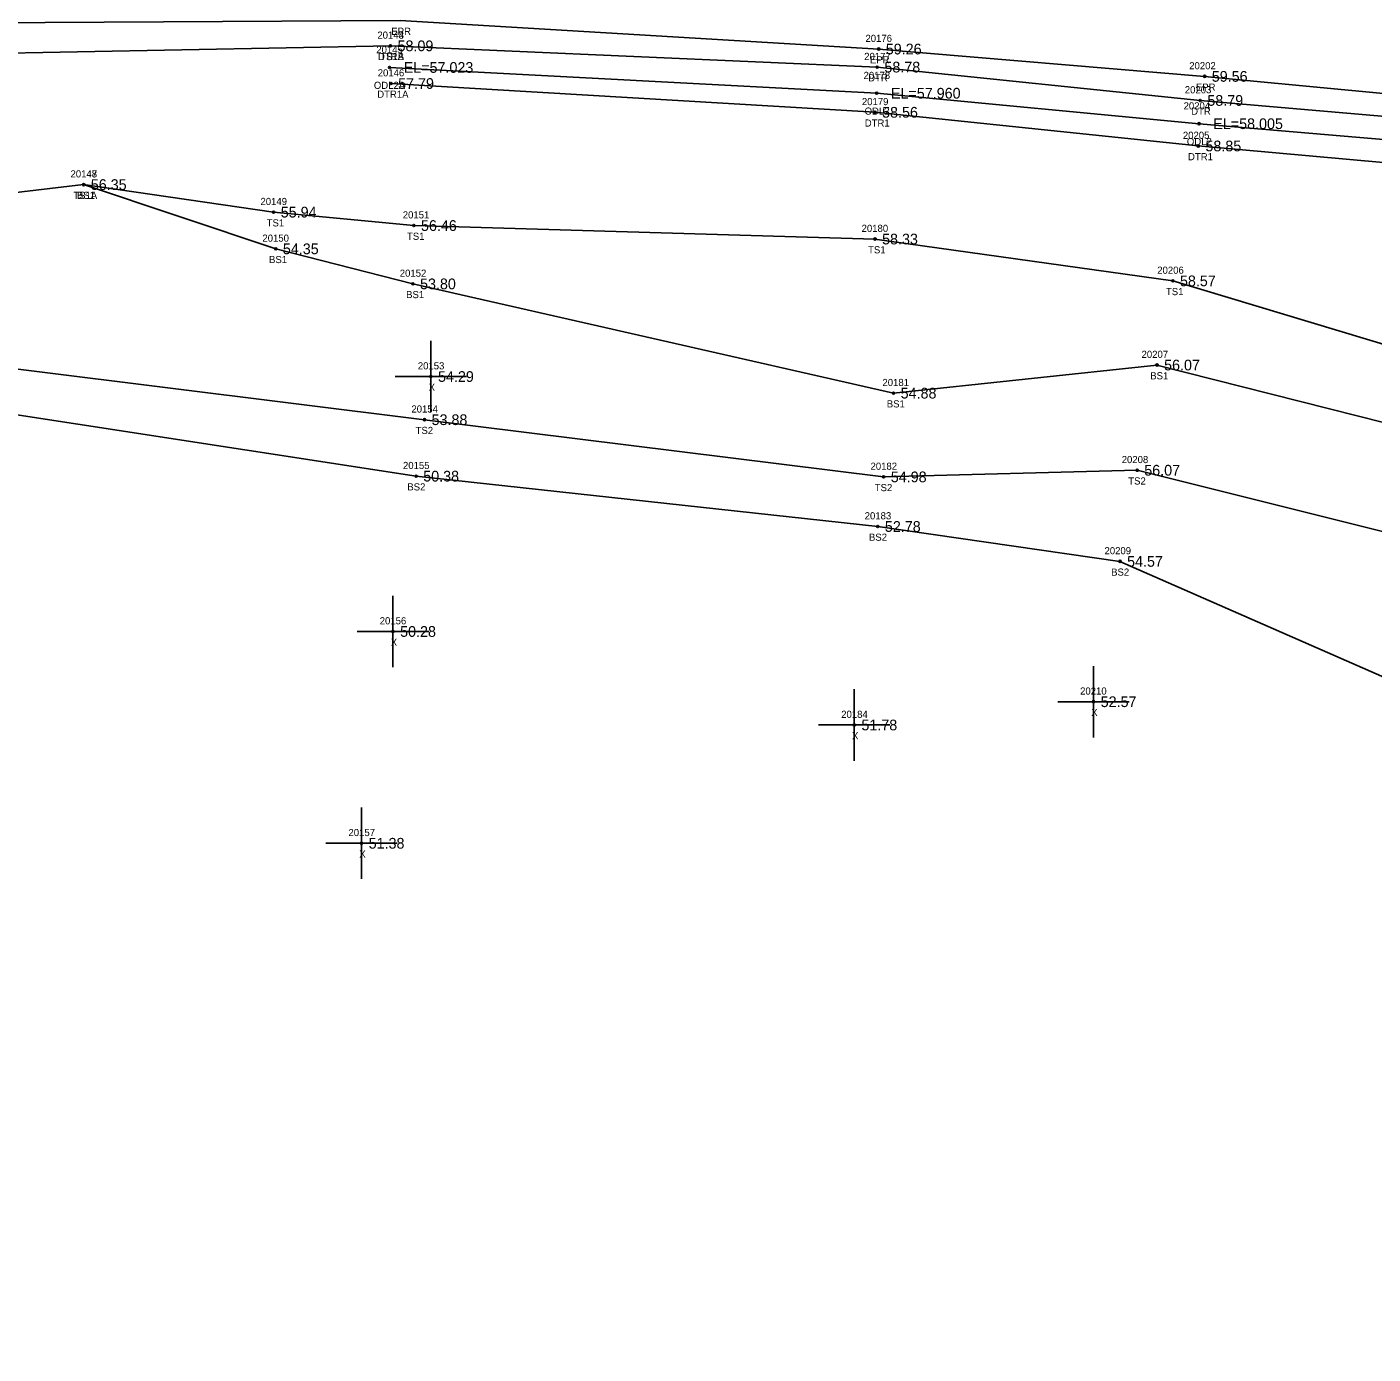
# Model space of a CAD drawing. Extents: x 2420351 to 2422725, y 845330 to 846558.
# Drawn here: x 2420630.1 to 2420818.7, y 845524.4 to 845710.4 of the extents above; entities that cross this region are included whole.
import ezdxf

# ---------------------------------------------------------------- set-up
doc = ezdxf.new("R2010")
doc.units = 0
for name, color, linetype in [('RD_DTM_BkLn2', 7, 'Continuous'), ('RD_DTM_BkLn_txCode', 7, 'Continuous'), ('RD_EX_H2O', 7, 'Continuous'), ('RD_EX_H2O_txCode', 7, 'Continuous'), ('RD_EX_Misc', 7, 'Continuous'), ('RD_EX_Misc_txCode', 7, 'Continuous'), ('RD_EX_Road', 7, 'Continuous'), ('RD_EX_Road_txCode', 7, 'Continuous'), ('RD_EX_TX_H2O_ELEV', 7, 'Continuous'), ('RD_EX_TX_Misc_ELEV', 7, 'Continuous'), ('RD_EX_TX_Road_ELEV', 7, 'Continuous'), ('RD_SMD_Locator', 7, 'Continuous')]:
    doc.layers.add(name, color=color, linetype=linetype)

msp = doc.modelspace()

# ---------------------------------------------------------------- linework, layer by layer
at = {"layer": 'RD_DTM_BkLn2'}
for points in [[(2420390.61, 845669.92), (2420441.98, 845686.33), (2420494.54, 845693.53), (2420554.96, 845697.51), (2420607.89, 845706.33), (2420681.02, 845707.72)], [(2420391.68, 845656.64), (2420445.21, 845668.26), (2420499.47, 845673.15), (2420555.79, 845685.67), (2420611.25, 845685.1), (2420638.03, 845688.28), (2420664.95, 845679.28), (2420684.17, 845674.37), (2420751.52, 845659.06), (2420788.44, 845663), (2420892.57, 845636.64), (2420995.04, 845591.46), (2421010.85, 845555.52)], [(2420638.03, 845688.28), (2420664.65, 845684.42), (2420684.3, 845682.54), (2420748.92, 845680.65), (2420790.66, 845674.79), (2420895.81, 845643.13), (2420998.36, 845598.73), (2421012.82, 845561.7)], [(2420554.48, 845663.6), (2420612.71, 845664.41), (2420685.79, 845655.34), (2420750.14, 845647.33), (2420785.66, 845648.26), (2420885.87, 845623.22), (2421008.49, 845539.14)], [(2420554.18, 845658.61), (2420613.14, 845658.42), (2420684.62, 845647.43), (2420749.31, 845640.38), (2420783.25, 845635.49), (2420872.47, 845596.38), (2421005.56, 845524.43)]]:
    msp.add_lwpolyline(points, dxfattribs=at)
at = {"layer": 'RD_EX_H2O'}
for points in [[(2420681.02, 845707.72), (2420749.24, 845704.74), (2420794.5, 845700.07), (2420899.98, 845690.96), (2421017.54, 845678.31), (2421112.89, 845668.07), (2421174.6, 845666.39), (2421234.64, 845664.08), (2421293.38, 845665.28), (2421351.67, 845667.88), (2421422.34, 845677.35), (2421426.88, 845673.47), (2421424.22, 845667.22)], [(2420680.88, 845704.69), (2420749.16, 845701.08), (2420794.33, 845696.81), (2420899.79, 845687.85), (2421017.53, 845674.81), (2421112.48, 845665.13), (2421174.04, 845661.58), (2421234.82, 845660.24), (2421294.09, 845659.38), (2421352.01, 845663.24), (2421417.66, 845672.42), (2421424.72, 845673.17)], [(2420681.1, 845702.44), (2420748.92, 845698.41), (2420794.23, 845693.69), (2420899.45, 845684.25), (2421017.43, 845671.31), (2421111.87, 845660.39), (2421174.2, 845656.63), (2421235.06, 845654.38), (2421294.9, 845653.67), (2421353.19, 845655.89), (2421424.22, 845667.22)]]:
    msp.add_lwpolyline(points, dxfattribs=at)
at = {"layer": 'RD_EX_Misc'}
for p, q in [((2420686.69, 845656.39), (2420686.69, 845666.39)), ((2420681.69, 845661.39), (2420691.69, 845661.39)), ((2420681.38, 845620.67), (2420681.38, 845630.67)), ((2420676.38, 845625.67), (2420686.38, 845625.67)), ((2420779.55, 845610.83), (2420779.55, 845620.83)), ((2420746.02, 845607.57), (2420746.02, 845617.57)), ((2420774.55, 845615.83), (2420784.55, 845615.83)), ((2420741.02, 845612.57), (2420751.02, 845612.57)), ((2420676.97, 845591), (2420676.97, 845601)), ((2420671.97, 845596), (2420681.97, 845596))]:
    msp.add_line(p, q, dxfattribs=at)
at = {"layer": 'RD_EX_Road'}
msp.add_lwpolyline([(2420388.28, 845680.39), (2420441.29, 845692.04), (2420492.62, 845700.7), (2420553.92, 845707.41), (2420607.69, 845710.85), (2420682.38, 845711.26), (2420749.44, 845707.27), (2420795.12, 845703.44), (2420900.28, 845693.42), (2421017.17, 845682.19), (2421113.9, 845672.97), (2421174.87, 845668.16), (2421234.59, 845666.13), (2421293, 845667.25), (2421351.24, 845671.5), (2421419.82, 845681.17), (2421463.19, 845688.63), (2421558.82, 845713.18), (2421614.57, 845730.45), (2421670.73, 845751.42), (2421735.61, 845780.5), (2421750.75, 845787.87), (2421744.67, 845798.22), (2421739.21, 845808.11)], dxfattribs=at)
at = {"layer": 'RD_SMD_Locator'}
for centre in [(2420681.02, 845707.72), (2420681.02, 845707.72), (2420749.44, 845707.27), (2420680.88, 845704.69), (2420749.24, 845704.74), (2420795.12, 845703.44), (2420681.1, 845702.44), (2420749.16, 845701.08), (2420794.5, 845700.07), (2420748.92, 845698.41), (2420794.33, 845696.81), (2420794.23, 845693.69), (2420638.03, 845688.28), (2420638.03, 845688.28), (2420664.65, 845684.42), (2420684.3, 845682.54), (2420748.92, 845680.65), (2420664.95, 845679.28), (2420790.66, 845674.79), (2420684.17, 845674.37), (2420686.69, 845661.39), (2420788.44, 845663), (2420751.52, 845659.06), (2420685.79, 845655.34), (2420785.66, 845648.26), (2420684.62, 845647.43), (2420750.14, 845647.33), (2420749.31, 845640.38), (2420783.25, 845635.49), (2420681.38, 845625.67), (2420779.55, 845615.83), (2420746.02, 845612.57), (2420676.97, 845596)]:
    msp.add_circle(centre, 0.15, dxfattribs=at)

# ---------------------------------------------------------------- texts
at = {"layer": 'RD_DTM_BkLn_txCode'}
for s, p in [('20143', (2420679.19, 845708.72)), ('TS1B', (2420679.59, 845705.72)), ('20147', (2420636.19, 845689.28)), ('20148', (2420636.19, 845689.28)), ('TS1A', (2420636.58, 845686.28)), ('BS1', (2420637.08, 845686.28)), ('20149', (2420662.81, 845685.42)), ('20151', (2420682.75, 845683.54)), ('TS1', (2420663.68, 845682.42)), ('20180', (2420747.05, 845681.65)), ('20150', (2420663.08, 845680.28)), ('TS1', (2420683.34, 845680.54)), ('TS1', (2420747.96, 845678.65)), ('BS1', (2420664.01, 845677.28)), ('20206', (2420788.48, 845675.79)), ('20152', (2420682.33, 845675.37)), ('BS1', (2420683.22, 845672.37)), ('TS1', (2420789.7, 845672.79)), ('20207', (2420786.28, 845664)), ('BS1', (2420787.5, 845661)), ('20181', (2420749.97, 845660.06)), ('BS1', (2420750.58, 845657.06)), ('20154', (2420683.96, 845656.34)), ('TS2', (2420684.55, 845653.34)), ('20208', (2420783.5, 845649.26)), ('20155', (2420682.78, 845648.43)), ('20182', (2420748.3, 845648.33)), ('BS2', (2420683.39, 845645.43)), ('TS2', (2420784.42, 845646.26)), ('TS2', (2420748.89, 845645.33)), ('20183', (2420747.48, 845641.38)), ('BS2', (2420748.08, 845638.38)), ('20209', (2420781.09, 845636.49)), ('BS2', (2420782.02, 845633.49))]:
    msp.add_text(s, height=1, dxfattribs=at).set_placement(p)
at = {"layer": 'RD_EX_H2O_txCode'}
for s, p in [('20144', (2420679.19, 845708.72)), ('20145', (2420679.04, 845706.69)), ('DTRA', (2420679.27, 845705.72)), ('20177', (2420747.41, 845705.74)), ('20146', (2420679.24, 845703.44)), ('20178', (2420747.33, 845703.08)), ('DTR', (2420747.97, 845702.74)), ('ODL2A', (2420678.7, 845701.69)), ('DTR1A', (2420679.17, 845700.44)), ('20203', (2420792.34, 845701.07)), ('20179', (2420747.09, 845699.41)), ('20204', (2420792.17, 845698.81)), ('ODL2', (2420747.47, 845698.08)), ('DTR1', (2420747.49, 845696.41)), ('DTR', (2420793.23, 845698.07)), ('20205', (2420792.07, 845694.69)), ('ODL2', (2420792.63, 845693.81)), ('DTR1', (2420792.79, 845691.69))]:
    msp.add_text(s, height=1, dxfattribs=at).set_placement(p)
at = {"layer": 'RD_EX_Misc_txCode'}
for s, p in [('20153', (2420684.86, 845662.39)), ('X', (2420686.38, 845659.39)), ('20156', (2420679.52, 845626.67)), ('X', (2420681.07, 845623.67)), ('20210', (2420777.67, 845616.83)), ('20184', (2420744.19, 845613.57)), ('X', (2420779.23, 845613.83)), ('X', (2420745.71, 845610.57)), ('20157', (2420675.14, 845597)), ('X', (2420676.66, 845594))]:
    msp.add_text(s, height=1, dxfattribs=at).set_placement(p)
at = {"layer": 'RD_EX_Road_txCode'}
for s, p in [('EPR', (2420681.15, 845709.26)), ('20176', (2420747.59, 845708.27)), ('EPR', (2420748.22, 845705.27)), ('20202', (2420792.96, 845704.44)), ('EPR', (2420793.89, 845701.44))]:
    msp.add_text(s, height=1, dxfattribs=at).set_placement(p)
at = {"layer": 'RD_EX_TX_H2O_ELEV'}
for s, p in [('58.09', (2420682.02, 845706.97)), ('EL=57.023', (2420682.88, 845703.94)), ('58.78', (2420750.24, 845703.99)), ('57.79', (2420682.1, 845701.69)), ('EL=57.960', (2420751.16, 845700.33)), ('58.79', (2420795.5, 845699.32)), ('58.56', (2420749.92, 845697.66)), ('EL=58.005', (2420796.33, 845696.06)), ('58.85', (2420795.23, 845692.94))]:
    msp.add_text(s, height=1.5, dxfattribs=at).set_placement(p)
at = {"layer": 'RD_EX_TX_Misc_ELEV'}
for s, p in [('58.09', (2420682.02, 845706.97)), ('56.35', (2420639.03, 845687.53)), ('56.35', (2420639.03, 845687.53)), ('55.94', (2420665.65, 845683.67)), ('56.46', (2420685.3, 845681.79)), ('58.33', (2420749.92, 845679.9)), ('54.35', (2420665.95, 845678.53)), ('53.80', (2420685.17, 845673.62)), ('58.57', (2420791.66, 845674.04)), ('56.07', (2420789.44, 845662.25)), ('54.29', (2420687.69, 845660.64)), ('54.88', (2420752.52, 845658.31)), ('53.88', (2420686.79, 845654.59)), ('56.07', (2420786.66, 845647.51)), ('50.38', (2420685.62, 845646.68)), ('54.98', (2420751.14, 845646.58)), ('52.78', (2420750.31, 845639.63)), ('54.57', (2420784.25, 845634.74)), ('50.28', (2420682.38, 845624.92)), ('52.57', (2420780.55, 845615.08)), ('51.78', (2420747.02, 845611.82)), ('51.38', (2420677.97, 845595.25))]:
    msp.add_text(s, height=1.5, dxfattribs=at).set_placement(p)
at = {"layer": 'RD_EX_TX_Road_ELEV'}
for s, p in [('59.26', (2420750.44, 845706.52)), ('59.56', (2420796.12, 845702.69))]:
    msp.add_text(s, height=1.5, dxfattribs=at).set_placement(p)

doc.saveas('drawing.dxf')
